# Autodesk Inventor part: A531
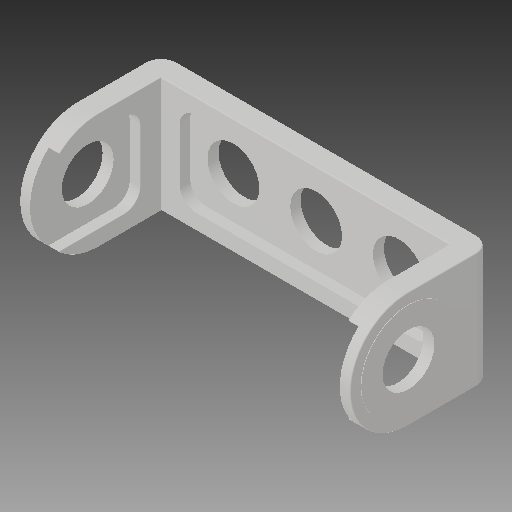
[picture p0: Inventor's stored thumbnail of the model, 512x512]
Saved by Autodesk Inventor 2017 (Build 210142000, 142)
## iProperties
Part Number: A531
Material: Générique
Document SubType Name: Modeling
Designer: ficho
Density: 1 g/cm^3
Appearance: Par défaut
Author: ficho
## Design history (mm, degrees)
feature "Solid1"
node "Solide1"
